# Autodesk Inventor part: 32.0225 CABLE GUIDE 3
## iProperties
Created: 2012-10
Part Number: 32.0225 CABLE GUIDE 3
Document SubType Name: Modeling
Designer: Administrator
Density: 1.4 g/cm^3
Material: PVC-Piping
Mass: 11.6076 g
Surface Area: 50.7651 cm^2
Volume: 8.29117 cm^3
Author: Administrator
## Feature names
1. Base1
